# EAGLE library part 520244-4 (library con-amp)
AMP connector
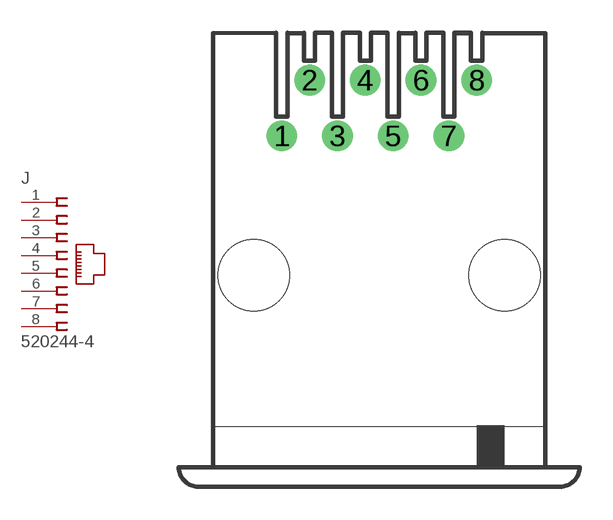
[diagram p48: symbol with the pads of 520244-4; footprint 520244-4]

Designator prefix J

## 520244-4 (OC_FARNELL: unknown; OC_NEWARK: unknown)  [520244-4]
1  1  pas
2  2  pas
3  3  pas
4  4  pas
5  5  pas
6  6  pas
7  7  pas
8  8  pas

## Footprint 520244-4 (pad centres in mm)
Modular Jack Keyed with Flanged
drill 0.889 round: 1 -4.445,6.35; 2 -3.175,8.89; 3 -1.905,6.35; 4 -0.635,8.89; 5 0.635,6.35; 6 1.905,8.89; 7 3.175,6.35; 8 4.445,8.89
hole 3.251 at -5.715,0
hole 3.251 at 5.715,0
